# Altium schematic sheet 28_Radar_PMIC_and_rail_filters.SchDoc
size 289 x 396 mm
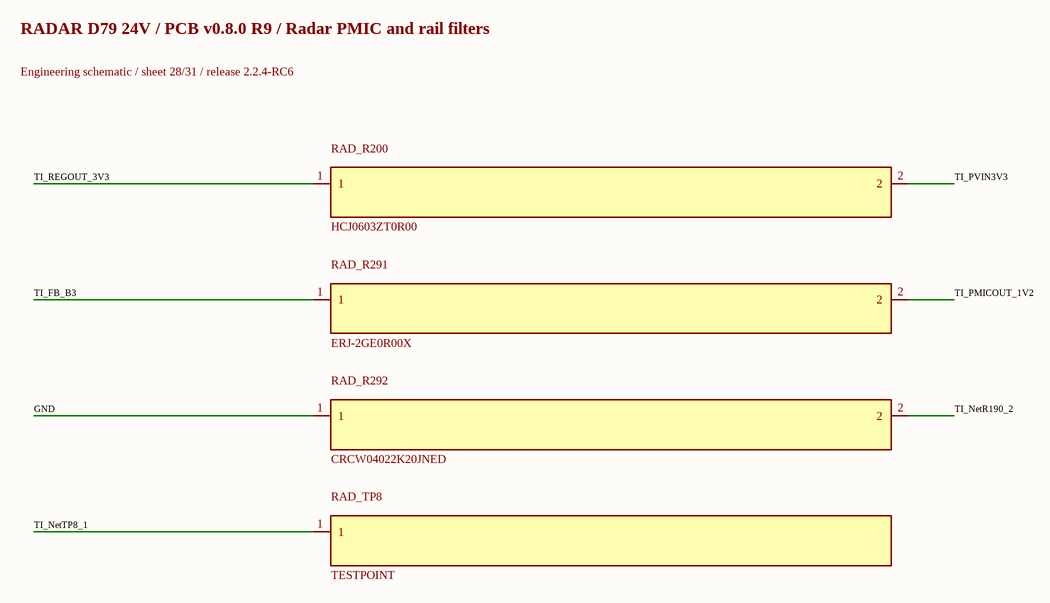
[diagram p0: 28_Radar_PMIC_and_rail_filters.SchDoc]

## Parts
RAD_R200  HCJ0603ZT0R00  [FP-HCJ0603ZT0R00_0603-MFG]
RAD_R291  ERJ-2GE0R00X  [0402L]
RAD_R292  CRCW04022K20JNED  [0402L]
RAD_TP8  TESTPOINT  [TP_25MIL-SMT]

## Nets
GND: RAD_R292.1
TI_FB_B3: RAD_R291.1
TI_NetR190_2: RAD_R292.2
TI_NetTP8_1: RAD_TP8.1
TI_PMICOUT_1V2: RAD_R291.2
TI_PVIN3V3: RAD_R200.2
TI_REGOUT_3V3: RAD_R200.1

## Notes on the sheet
- RADAR D79 24V / PCB v0.8.0 R9 / Radar PMIC and rail filters
- Engineering schematic / sheet 28/31 / release 2.2.4-RC6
